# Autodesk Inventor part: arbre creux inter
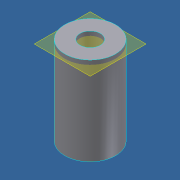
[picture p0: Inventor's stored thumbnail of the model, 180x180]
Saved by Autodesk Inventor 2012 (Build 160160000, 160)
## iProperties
Created: 2011-10
Part Number: arbre creux inter
Document SubType Name: Modeling
Designer: Laur
Density: 7.85 g/cm^3
Material: Acier
Mass: 0.140154 g
Surface Area: 0.558575 cm^2
Volume: 0.0178541 cm^3
Author: Laur
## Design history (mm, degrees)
sketch "Esquisse1"
  geometry: C1 r 0.5 at (0, 0); C2 r 1.25 at (0, 0); 1 further point
  constraints: 2 centre point, 2 coincident, 1 other
  dimensions: "d0" = 1 diameter of C1; "d1" = 2.5 diameter of C2
extrude "Extrusion1" new body sketch "Esquisse1" distance "d2" = 4.33; taper "d3" = 0 deg
node "Plan de construction1"
feature "Engrenage cylindrique1"
node "Solide1"
node "Corps solides"
node "Corps surfaciques"
other parameters: "d4" = -0.2
